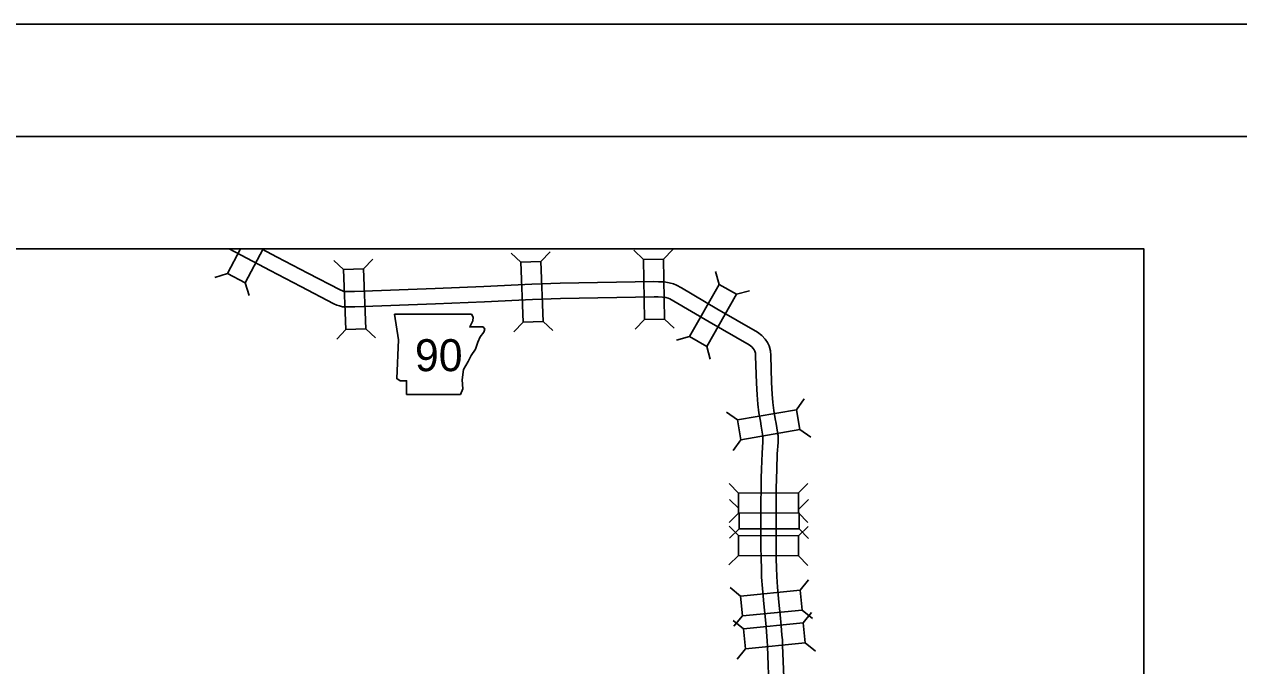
# Model space of a CAD drawing. Extents: x -0.3 to 2.65, y 0 to 1.9.
# Drawn here: x 0.1338 to 0.3593, y 0.7976 to 0.9167 of the extents above; entities that cross this region are included whole.
import ezdxf

# ---------------------------------------------------------------- set-up
doc = ezdxf.new("R2010")
doc.units = 0
for name, color, linetype in [('DSN_DRFT_DNC', 7, 'Continuous'), ('Level 21', 7, 'Continuous'), ('Level 22', 7, 'Continuous'), ('Level 38', 7, 'Continuous'), ('SHET_Border-Lines', 7, 'Continuous')]:
    doc.layers.add(name, color=color, linetype=linetype)

msp = doc.modelspace()

# ---------------------------------------------------------------- linework, layer by layer
at = {"layer": 'DSN_DRFT_DNC'}
msp.add_lwpolyline([(0.04166666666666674, 0.8750000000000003), (0.34166666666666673, 0.8750000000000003), (0.34166666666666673, 0.541666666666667), (0.04166666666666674, 0.541666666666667)], close=True, dxfattribs=at)
at = {"layer": 'Level 21'}
for points in [[(0.272141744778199, 0.7924518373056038), (0.2718029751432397, 0.8012743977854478), (0.27176802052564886, 0.802255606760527), (0.27168585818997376, 0.8030690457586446), (0.2715680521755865, 0.8048590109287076), (0.27139017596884, 0.8067741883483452), (0.2711175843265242, 0.8090947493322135), (0.27097644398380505, 0.8105432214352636), (0.27085482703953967, 0.811986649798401), (0.270705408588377, 0.8140389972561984), (0.2706672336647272, 0.8157453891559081), (0.2706210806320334, 0.8174067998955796), (0.2705862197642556, 0.8198778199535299), (0.2705974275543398, 0.8217348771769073), (0.2705993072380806, 0.8237845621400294), (0.27060024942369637, 0.8248096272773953), (0.2705962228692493, 0.8278381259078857), (0.27061891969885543, 0.8304864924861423), (0.27064492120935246, 0.832453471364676), (0.270720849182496, 0.8341370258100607), (0.27081516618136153, 0.8370849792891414), (0.2709542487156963, 0.839189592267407), (0.2709657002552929, 0.8399087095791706), (0.27096444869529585, 0.8400289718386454), (0.27093930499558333, 0.8401525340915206), (0.2708992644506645, 0.8406061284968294), (0.2706434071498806, 0.8421023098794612), (0.2704808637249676, 0.8429872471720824), (0.2702285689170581, 0.8445540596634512), (0.27000914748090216, 0.8461818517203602), (0.26989439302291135, 0.8478787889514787), (0.2697669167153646, 0.8500902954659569), (0.2695907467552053, 0.8550738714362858), (0.2695652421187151, 0.8556434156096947), (0.2694708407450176, 0.8559880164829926), (0.26935361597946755, 0.8562364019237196), (0.26917062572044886, 0.8565030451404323), (0.2688828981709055, 0.8568198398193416), (0.26839092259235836, 0.8571855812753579), (0.2609724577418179, 0.8614247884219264), (0.25443700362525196, 0.8652968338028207), (0.2536771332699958, 0.8656998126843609), (0.2533781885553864, 0.86583046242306), (0.2529472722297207, 0.8659559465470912), (0.2523194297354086, 0.8660414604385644), (0.2515101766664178, 0.8660901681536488), (0.25073900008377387, 0.8660913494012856), (0.23338178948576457, 0.8657868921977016), (0.22814764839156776, 0.8656030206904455), (0.2192849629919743, 0.8651746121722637), (0.21019156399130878, 0.8648019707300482), (0.19520731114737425, 0.8642545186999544), (0.1936239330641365, 0.8642428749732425), (0.19292923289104, 0.8642619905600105), (0.19234971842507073, 0.8643987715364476), (0.19187208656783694, 0.8645640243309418), (0.19127954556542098, 0.864818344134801), (0.1851788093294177, 0.8679954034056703), (0.1794882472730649, 0.87097626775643), (0.1751531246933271, 0.8732534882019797), (0.17183597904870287, 0.8749999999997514)], [(0.2749520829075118, 0.7925619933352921), (0.27461354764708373, 0.8013784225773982), (0.2745754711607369, 0.8024471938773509), (0.27448905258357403, 0.8033027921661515), (0.2743719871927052, 0.8050814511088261), (0.27418745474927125, 0.8070683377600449), (0.27391412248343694, 0.8093952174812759), (0.2737774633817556, 0.8107976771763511), (0.2736587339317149, 0.8122068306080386), (0.273515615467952, 0.8141726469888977), (0.27347885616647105, 0.8158158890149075), (0.2734330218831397, 0.8174656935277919), (0.2733988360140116, 0.8198891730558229), (0.2734099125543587, 0.8217250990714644), (0.27341180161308, 0.823781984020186), (0.27341274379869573, 0.8248102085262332), (0.2734087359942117, 0.8278279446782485), (0.2734312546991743, 0.8304558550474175), (0.27345658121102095, 0.8323715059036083), (0.2735313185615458, 0.8340286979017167), (0.273624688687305, 0.8369472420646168), (0.2737652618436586, 0.8390743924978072), (0.27377842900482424, 0.8399009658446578), (0.27377398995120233, 0.8403267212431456), (0.2737269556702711, 0.8405578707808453), (0.27369080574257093, 0.84096741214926), (0.2734127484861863, 0.8425934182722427), (0.2732526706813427, 0.843464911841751), (0.2730110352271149, 0.8449655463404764), (0.27280892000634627, 0.8464649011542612), (0.27270142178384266, 0.848054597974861), (0.2725765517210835, 0.850220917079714), (0.27240101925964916, 0.8551864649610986), (0.27236085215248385, 0.8560832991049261), (0.2721187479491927, 0.8569670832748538), (0.27180055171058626, 0.8576413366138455), (0.2713812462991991, 0.8582523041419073), (0.2707806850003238, 0.85891352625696), (0.26993317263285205, 0.8595435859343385), (0.2623870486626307, 0.8638557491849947), (0.25581341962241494, 0.8677504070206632), (0.2549008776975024, 0.8682343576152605), (0.25433846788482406, 0.8684801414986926), (0.2535334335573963, 0.868714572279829), (0.25259408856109, 0.868842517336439), (0.2515968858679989, 0.8689025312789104), (0.25071649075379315, 0.8689038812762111), (0.23330775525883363, 0.8685985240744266), (0.22803037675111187, 0.8684131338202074), (0.21915948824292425, 0.8679843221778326), (0.2100826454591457, 0.8676123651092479), (0.19514561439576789, 0.8670666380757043), (0.19365228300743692, 0.8670556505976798), (0.193294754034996, 0.8670654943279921), (0.19313455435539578, 0.8671033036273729), (0.19288783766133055, 0.867188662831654), (0.19248538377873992, 0.8673613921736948), (0.18648086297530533, 0.8704883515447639), (0.18079473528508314, 0.873466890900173), (0.17787617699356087, 0.8749999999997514)]]:
    msp.add_lwpolyline(points, dxfattribs=at)
at = {"layer": 'Level 22'}
msp.add_lwpolyline([(0.20258399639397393, 0.8628870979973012), (0.20329771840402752, 0.8581289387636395), (0.202980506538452, 0.8509124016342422), (0.2036149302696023, 0.8505158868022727), (0.20480447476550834, 0.8505158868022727), (0.20480447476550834, 0.8479782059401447), (0.21479661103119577, 0.8479782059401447), (0.21527241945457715, 0.849009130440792), (0.2151138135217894, 0.8506744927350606), (0.21535172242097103, 0.8525777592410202), (0.21622405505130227, 0.8540845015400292), (0.2167791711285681, 0.8551947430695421), (0.21757220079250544, 0.8563842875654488), (0.218048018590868, 0.8576531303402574), (0.21844453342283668, 0.8586840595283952), (0.21915826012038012, 0.8595563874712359), (0.21931686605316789, 0.8601115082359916), (0.2189996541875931, 0.8605080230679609), (0.21654126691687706, 0.8605080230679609), (0.21709638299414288, 0.8616182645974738), (0.21717568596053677, 0.8623319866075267), (0.21684681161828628, 0.8628801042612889)], close=True, dxfattribs=at)
at = {"layer": 'Level 38'}
for p, q in [((0.2524860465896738, 0.8730980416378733), (0.25420516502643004, 0.874878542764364)), ((0.19311812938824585, 0.8711578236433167), (0.1913053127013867, 0.8728428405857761)), ((0.19682814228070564, 0.8712933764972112), (0.19851315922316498, 0.8731061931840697)), ((0.2260384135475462, 0.8725082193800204), (0.22422796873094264, 0.8741957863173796)), ((0.22974861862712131, 0.872638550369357), (0.23143618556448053, 0.8744489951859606)), ((0.24877413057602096, 0.8730329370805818), (0.24699362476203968, 0.874752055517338)), ((0.1715746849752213, 0.8704313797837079), (0.16921149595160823, 0.8696958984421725)), ((0.2628310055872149, 0.8683962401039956), (0.2621798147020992, 0.8707840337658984)), ((0.17486132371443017, 0.8687049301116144), (0.17559680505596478, 0.8663417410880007)), ((0.2660543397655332, 0.8665542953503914), (0.2684421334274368, 0.8672054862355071)), ((0.22642940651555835, 0.8613776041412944), (0.22474183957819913, 0.8595671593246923)), ((0.23013961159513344, 0.8615079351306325), (0.23195005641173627, 0.8598203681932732)), ((0.24896944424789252, 0.8618971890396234), (0.24725032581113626, 0.8601166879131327)), ((0.25268136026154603, 0.8619622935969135), (0.25446186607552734, 0.8602431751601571)), ((0.19352478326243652, 0.8600277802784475), (0.19183976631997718, 0.8582149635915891)), ((0.1972347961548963, 0.8601633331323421), (0.19904761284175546, 0.8584783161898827)), ((0.2573051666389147, 0.8587262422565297), (0.25491737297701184, 0.858075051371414)), ((0.2605285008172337, 0.856884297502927), (0.26117969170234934, 0.8544965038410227)), ((0.27720425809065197, 0.8451162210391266), (0.2786343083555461, 0.847136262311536)), ((0.26622612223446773, 0.8432388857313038), (0.26420608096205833, 0.8446689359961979)), ((0.2778300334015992, 0.8414568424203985), (0.27985007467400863, 0.8400267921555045)), ((0.26685189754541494, 0.8395795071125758), (0.2654218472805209, 0.8375594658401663)), ((0.26643128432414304, 0.8296818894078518), (0.26467888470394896, 0.8314296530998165)), ((0.27756874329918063, 0.8296966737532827), (0.27931650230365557, 0.8314490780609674)), ((0.2664791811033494, 0.8267833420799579), (0.26477718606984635, 0.8284884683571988)), ((0.277685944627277, 0.8267493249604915), (0.2794148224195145, 0.8284750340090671)), ((0.26643621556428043, 0.8259693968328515), (0.26468845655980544, 0.8242169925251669)), ((0.26652497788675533, 0.8259903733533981), (0.26652225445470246, 0.8230242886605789)), ((0.27757367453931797, 0.8259841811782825), (0.27932607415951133, 0.8242364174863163)), ((0.2776597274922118, 0.8230140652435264), (0.2776624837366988, 0.8260164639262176)), ((0.2664351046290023, 0.8217733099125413), (0.2646956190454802, 0.8235339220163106)), ((0.26652225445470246, 0.8230242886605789), (0.26477056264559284, 0.8212758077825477)), ((0.26652225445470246, 0.8230242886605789), (0.2776597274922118, 0.8230140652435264)), ((0.27757235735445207, 0.8217060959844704), (0.27933296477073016, 0.8234455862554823)), ((0.2776597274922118, 0.8230140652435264), (0.2794082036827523, 0.821262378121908)), ((0.26641269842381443, 0.8180608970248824), (0.26465209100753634, 0.8163214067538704)), ((0.27754995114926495, 0.8179936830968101), (0.2792894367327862, 0.8162330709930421)), ((0.2667933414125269, 0.8105524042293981), (0.2648817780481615, 0.8121245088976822)), ((0.2778783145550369, 0.8116325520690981), (0.2794504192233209, 0.8135441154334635)), ((0.2782383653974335, 0.8079375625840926), (0.28014992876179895, 0.8063654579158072)), ((0.2784414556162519, 0.8055923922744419), (0.28000680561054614, 0.8075094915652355)), ((0.26736037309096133, 0.8044731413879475), (0.26544327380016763, 0.8060384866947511)), ((0.26715339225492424, 0.8068574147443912), (0.2655812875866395, 0.8049458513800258)), ((0.26773345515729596, 0.8007794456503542), (0.26616810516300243, 0.7988623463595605)), ((0.2788145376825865, 0.8018986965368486), (0.2807316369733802, 0.800333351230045))]:
    msp.add_line(p, q, dxfattribs=at)
msp.add_lwpolyline([(0.1739745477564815, 0.8749999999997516), (0.1715746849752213, 0.8704313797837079), (0.17486132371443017, 0.8687049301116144), (0.17816807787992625, 0.8749999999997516)], dxfattribs=at)
for points in [[(0.23013961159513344, 0.8615079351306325), (0.22974861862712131, 0.872638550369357), (0.2260384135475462, 0.8725082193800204), (0.22642940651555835, 0.8613776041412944)], [(0.24877413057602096, 0.8730329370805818), (0.24896944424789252, 0.8618971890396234), (0.25268136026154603, 0.8619622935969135), (0.2524860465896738, 0.8730980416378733)], [(0.1972347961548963, 0.8601633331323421), (0.19682814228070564, 0.8712933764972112), (0.19311812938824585, 0.8711578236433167), (0.19352478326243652, 0.8600277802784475)], [(0.2605285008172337, 0.856884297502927), (0.2660543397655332, 0.8665542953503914), (0.2628310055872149, 0.8683962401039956), (0.2573051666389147, 0.8587262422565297)], [(0.26685189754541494, 0.8395795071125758), (0.2778300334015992, 0.8414568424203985), (0.27720425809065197, 0.8451162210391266), (0.26622612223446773, 0.8432388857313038)], [(0.26643621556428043, 0.8259693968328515), (0.27757367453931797, 0.8259841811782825), (0.27756874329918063, 0.8296966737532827), (0.26643128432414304, 0.8296818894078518)], [(0.27757235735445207, 0.8217060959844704), (0.2664351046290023, 0.8217733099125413), (0.26641269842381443, 0.8180608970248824), (0.27754995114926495, 0.8179936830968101)], [(0.26715339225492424, 0.8068574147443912), (0.2782383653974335, 0.8079375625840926), (0.2778783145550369, 0.8116325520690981), (0.2667933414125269, 0.8105524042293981)], [(0.26773345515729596, 0.8007794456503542), (0.2788145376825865, 0.8018986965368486), (0.2784414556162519, 0.8055923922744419), (0.26736037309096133, 0.8044731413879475)]]:
    msp.add_lwpolyline(points, close=True, dxfattribs=at)
at = {"layer": 'SHET_Border-Lines'}
for points in [[(0, 0), (1.416666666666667, 0), (1.416666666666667, 0.9166666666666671), (0, 0.9166666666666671)], [(0.02083333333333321, 0.02083333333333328), (1.3958333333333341, 0.02083333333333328), (1.3958333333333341, 0.8958333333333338), (0.02083333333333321, 0.8958333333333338)]]:
    msp.add_lwpolyline(points, close=True, dxfattribs=at)

# ---------------------------------------------------------------- texts
at = {"layer": 'Level 22'}
msp.add_text('90', height=0.005939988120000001, dxfattribs=at).set_placement((0.20635447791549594, 0.8522889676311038))

doc.saveas('drawing.dxf')
